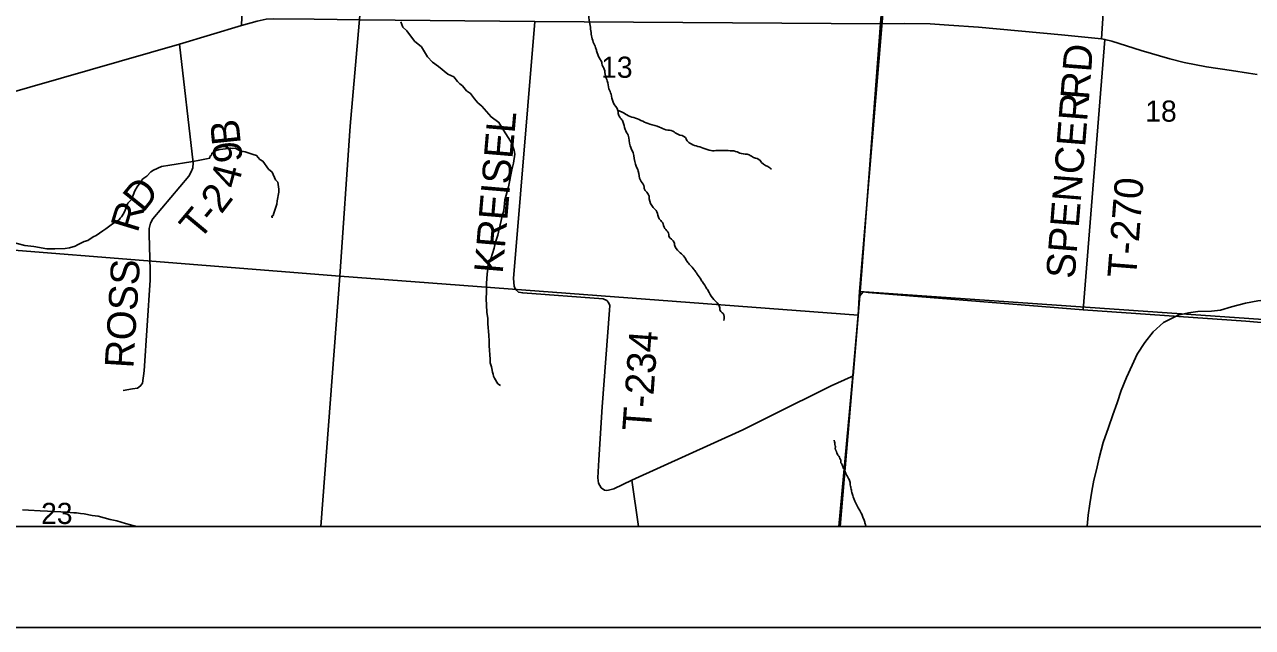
# Model space of a CAD drawing. Extents: x 0 to 42.5, y 0 to 22.
# Drawn here: x 4.279 to 5.494, y 14 to 14.597 of the extents above; entities that cross this region are included whole.
import ezdxf

# ---------------------------------------------------------------- set-up
doc = ezdxf.new("R2010")
doc.units = 0
for name, color, linetype in [('GM_X_County_Road', 7, 'Continuous'), ('GM_X_Interchange_Ramps', 7, 'Continuous'), ('GM_X_Minor_River', 7, 'Continuous'), ('GM_X_Section', 7, 'Continuous'), ('GM_X_Section_Text', 7, 'Continuous'), ('GM_X_State_Route', 7, 'Continuous'), ('GM_X_Township_Road', 7, 'Continuous'), ('GM_X_Township_Road_Text', 7, 'Continuous'), ('GM_X_Unincorporated', 7, 'Continuous'), ('SH_Cut_Line', 7, 'Continuous'), ('SH_Data', 7, 'Continuous')]:
    doc.layers.add(name, color=color, linetype=linetype)

msp = doc.modelspace()

# ---------------------------------------------------------------- linework, layer by layer
at = {"layer": 'GM_X_County_Road'}
msp.add_line((4.8867, 14.1), (4.88, 14.1456), dxfattribs=at)
for points in [[(5.097, 14.2481), (5.0988, 14.2489), (5.1055, 14.328), (5.1087, 14.332), (5.1139, 14.3316), (5.3266, 14.3143), (5.4875, 14.303), (5.579, 14.2953)], [(4.88, 14.1456), (4.9899, 14.1955), (5.018, 14.2096), (5.0772, 14.239), (5.097, 14.2481)]]:
    msp.add_lwpolyline(points, dxfattribs=at)
at = {"layer": 'GM_X_Interchange_Ramps'}
for points in [[(2.1, 14.1), (5.0849, 14.1), (5.0987, 14.2492), (5.1054, 14.3283), (5.1076, 14.3533), (5.1259, 14.5975), (5.1421, 14.8012), (5.162, 15.0772)], [(5.162, 15.0772), (5.1421, 14.8012), (5.1259, 14.5975), (5.1076, 14.3533), (5.1054, 14.3283), (5.0987, 14.2492), (5.0849, 14.1), (8.0699, 14.1)]]:
    msp.add_lwpolyline(points, dxfattribs=at)
at = {"layer": 'GM_X_Minor_River'}
for points in [[(4.6515, 14.5993), (4.6533, 14.5941), (4.6574, 14.5905), (4.6651, 14.5802), (4.6719, 14.5746), (4.678, 14.5645), (4.6829, 14.5593), (4.6887, 14.5551), (4.6979, 14.5474), (4.7039, 14.5448), (4.7075, 14.5402), (4.7097, 14.5379), (4.7124, 14.536), (4.7165, 14.531), (4.7204, 14.5285), (4.7242, 14.523), (4.7275, 14.5192), (4.7317, 14.5157), (4.7408, 14.5052), (4.7485, 14.4998), (4.7547, 14.4893), (4.7582, 14.4837), (4.7611, 14.4795), (4.7636, 14.4718), (4.7642, 14.4682), (4.763, 14.4593), (4.7614, 14.4529), (4.7581, 14.4359), (4.7542, 14.4231), (4.7534, 14.4127), (4.7513, 14.4058), (4.7474, 14.3882), (4.7449, 14.3803), (4.7439, 14.3754), (4.7406, 14.3649), (4.7383, 14.3608), (4.7379, 14.3587), (4.7374, 14.3572), (4.7374, 14.3545), (4.7369, 14.35), (4.7363, 14.3404), (4.7361, 14.3317), (4.7358, 14.3256), (4.7365, 14.312), (4.7374, 14.3056), (4.7375, 14.3006), (4.7384, 14.2893), (4.7387, 14.2832), (4.7389, 14.2787), (4.7399, 14.2655), (4.7399, 14.2617), (4.7412, 14.2579), (4.7414, 14.2562), (4.7423, 14.2527), (4.7429, 14.2507), (4.7432, 14.2486), (4.7442, 14.2467), (4.7473, 14.2411), (4.75, 14.2394)], [(4.2642, 14.3819), (4.2794, 14.3778), (4.2883, 14.377), (4.3012, 14.3748), (4.3092, 14.3746), (4.3195, 14.3751), (4.3237, 14.3756), (4.3294, 14.3773), (4.3317, 14.3786), (4.3382, 14.3818), (4.3418, 14.3829), (4.3471, 14.3865), (4.35, 14.388), (4.3567, 14.3925), (4.3595, 14.3944), (4.3662, 14.3994), (4.3727, 14.4034), (4.374, 14.4049), (4.375, 14.4064), (4.3775, 14.41), (4.3788, 14.413), (4.3815, 14.4197), (4.3851, 14.4236), (4.3882, 14.432), (4.3905, 14.4361), (4.3961, 14.4439), (4.4003, 14.4467), (4.4041, 14.4509), (4.4067, 14.4524), (4.4148, 14.4561), (4.4231, 14.4576), (4.4437, 14.4607), (4.4509, 14.4621), (4.4625, 14.4645), (4.4625, 14.4659), (4.4641, 14.4674), (4.4644, 14.4691), (4.4658, 14.47), (4.466, 14.4713), (4.4723, 14.473), (4.4755, 14.4734), (4.4831, 14.4743), (4.4854, 14.4739), (4.4877, 14.4742), (4.4926, 14.4717), (4.4975, 14.4707), (4.5055, 14.468), (4.5088, 14.4671), (4.512, 14.4632), (4.515, 14.4613), (4.5205, 14.4535), (4.5241, 14.4504), (4.5275, 14.443), (4.5299, 14.4405), (4.5307, 14.4336), (4.5308, 14.4306), (4.5293, 14.4223), (4.5287, 14.419), (4.526, 14.4101), (4.5252, 14.4078), (4.5239, 14.4071), (4.5243, 14.4054)], [(5.3303, 14.1), (5.3303, 14.1003), (5.3315, 14.111), (5.3331, 14.1223), (5.3351, 14.1348), (5.3371, 14.1458), (5.3395, 14.156), (5.3422, 14.1678), (5.3461, 14.1829), (5.3515, 14.198), (5.3558, 14.2105), (5.3601, 14.2223), (5.3639, 14.2344), (5.3694, 14.2472), (5.3748, 14.2597), (5.3798, 14.2703), (5.3874, 14.282), (5.3958, 14.2925), (5.4058, 14.3016), (5.4206, 14.309), (5.4308, 14.3112), (5.4399, 14.3127), (5.4535, 14.3129), (5.4623, 14.314), (5.4733, 14.3173), (5.4869, 14.321)], [(5.4869, 14.321), (5.4994, 14.3232), (5.5112, 14.3246), (5.5206, 14.3241), (5.5346, 14.324), (5.5471, 14.3232), (5.557, 14.3223), (5.5675, 14.3211), (5.5804, 14.3191), (5.5899, 14.3175), (5.6137, 14.3143), (5.6223, 14.3104), (5.6291, 14.3005), (5.6339, 14.2875), (5.6365, 14.2777), (5.6383, 14.2685), (5.6405, 14.2594), (5.6423, 14.2495), (5.6509, 14.2404), (5.6584, 14.2316), (5.661, 14.2205), (5.6654, 14.2087), (5.6695, 14.1977), (5.6732, 14.1893)], [(4.2771, 14.1164), (4.2832, 14.1161), (4.2946, 14.1155), (4.302, 14.115), (4.315, 14.1144), (4.3207, 14.114), (4.3281, 14.1133), (4.3306, 14.1135), (4.3347, 14.1127), (4.3382, 14.1123), (4.3461, 14.1109), (4.352, 14.11), (4.3638, 14.1068), (4.3705, 14.1055), (4.3792, 14.1027), (4.3839, 14.1017), (4.3907, 14.1)]]:
    msp.add_lwpolyline(points, dxfattribs=at)
for points in [[(4.8478, 15.0093), (4.8579, 14.9979), (4.8659, 14.9923), (4.8672, 14.9887), (4.8723, 14.9856), (4.8736, 14.9846), (4.873, 14.9746), (4.8718, 14.9669), (4.8677, 14.9406), (4.8634, 14.9244), (4.862, 14.9152), (4.8598, 14.8967), (4.86, 14.8914), (4.8604, 14.8749), (4.8609, 14.8662), (4.8611, 14.8611), (4.8623, 14.849), (4.8628, 14.8428), (4.8632, 14.8388), (4.865, 14.8278), (4.8659, 14.8242), (4.8674, 14.8193), (4.8687, 14.8151), (4.8686, 14.8075), (4.8676, 14.7981), (4.8555, 14.7663), (4.8535, 14.7541), (4.8451, 14.7279), (4.8418, 14.7166), (4.8412, 14.7107), (4.8409, 14.6962), (4.841, 14.692), (4.8409, 14.6684), (4.8403, 14.6616), (4.84, 14.6569), (4.839, 14.6459), (4.8384, 14.6414), (4.8372, 14.6344), (4.8364, 14.6261), (4.8364, 14.6231), (4.8366, 14.6186), (4.8366, 14.6165), (4.8369, 14.614), (4.8372, 14.6074), (4.8381, 14.5991), (4.8392, 14.5921), (4.8418, 14.5793), (4.8442, 14.5738), (4.8451, 14.5706), (4.8479, 14.5634), (4.8499, 14.5601), (4.851, 14.5558), (4.8527, 14.5525), (4.8538, 14.5459), (4.8557, 14.541), (4.8573, 14.533), (4.8595, 14.5277), (4.8614, 14.5197), (4.8662, 14.5115), (4.8668, 14.5075), (4.8686, 14.5043), (4.8712, 14.5005), (4.8734, 14.4927), (4.8762, 14.4872), (4.8784, 14.4765), (4.8812, 14.4697), (4.8836, 14.4583), (4.8864, 14.4515), (4.8884, 14.4426), (4.8918, 14.4372), (4.8923, 14.4344), (4.897, 14.4269), (4.8973, 14.4241), (4.9012, 14.4157), (4.9046, 14.4113), (4.907, 14.4045), (4.9102, 14.4007), (4.9126, 14.3948), (4.9162, 14.3902), (4.9167, 14.3873), (4.9218, 14.381), (4.9223, 14.3786), (4.9268, 14.3717), (4.9311, 14.3677), (4.9347, 14.3621), (4.9375, 14.3587), (4.9418, 14.3539), (4.9438, 14.3508), (4.9476, 14.3455), (4.9498, 14.3419), (4.9543, 14.3352), (4.9565, 14.3314), (4.961, 14.3245), (4.9668, 14.3171), (4.9673, 14.3135), (4.9702, 14.3106), (4.9711, 14.3039)], [(4.8662, 14.5115), (4.8711, 14.5097), (4.8766, 14.5064), (4.8837, 14.5039), (4.8978, 14.498), (4.9073, 14.4952), (4.9137, 14.4925), (4.9206, 14.4911), (4.9255, 14.488), (4.933, 14.4847), (4.9342, 14.4824), (4.9373, 14.4793), (4.9505, 14.4744), (4.9584, 14.4718), (4.9645, 14.4719), (4.9754, 14.4718), (4.9826, 14.4711), (4.9884, 14.4689), (4.996, 14.4677), (5.0005, 14.4652), (5.0071, 14.4621), (5.0084, 14.4601), (5.0165, 14.4549), (5.0181, 14.4536)]]:
    msp.add_spline(points, degree=3, dxfattribs=at)
msp.add_open_spline([(5.1114, 14.1), (5.1113, 14.1007), (5.1113, 14.1014), (5.111, 14.1021), (5.1097, 14.1062), (5.1083, 14.1103), (5.1064, 14.1141), (5.1055, 14.1158), (5.1045, 14.1174), (5.1036, 14.119), (5.1022, 14.1217), (5.1008, 14.1244), (5.0997, 14.1272), (5.098, 14.1315), (5.0972, 14.1359), (5.0962, 14.1403), (5.0959, 14.1419), (5.0961, 14.1436), (5.0955, 14.1451), (5.0944, 14.1475), (5.0931, 14.1499), (5.0919, 14.1523), (5.0903, 14.1557), (5.0887, 14.1591), (5.0871, 14.1626), (5.0866, 14.1636), (5.0868, 14.1649), (5.0864, 14.166), (5.0854, 14.1684), (5.0838, 14.1705), (5.0828, 14.1728), (5.0826, 14.1735), (5.0823, 14.1741), (5.0821, 14.1748), (5.0818, 14.1754), (5.0814, 14.176), (5.0812, 14.1767), (5.0809, 14.1773), (5.0815, 14.178), (5.0814, 14.1787), (5.081, 14.1809), (5.0806, 14.183), (5.0803, 14.1852)], degree=3, dxfattribs=at)
at = {"layer": 'GM_X_Section'}
for points in [[(4.1061, 14.8789), (4.6315, 14.8399), (4.6015, 14.4962), (4.591, 14.3476), (4.0702, 14.3893)], [(5.6186, 14.8156), (5.5806, 14.2995), (5.1051, 14.3325), (5.1432, 14.7839), (5.1456, 14.8014), (5.149, 14.8472)], [(5.1456, 14.8014), (5.1432, 14.7839), (5.1051, 14.3325), (5.1039, 14.3089), (4.591, 14.3476), (4.6015, 14.4962), (4.6315, 14.8399)]]:
    msp.add_lwpolyline(points, close=True, dxfattribs=at)
at = {"layer": 'GM_X_State_Route'}
msp.add_line((4.4324, 14.5772), (4.4938, 14.5956), dxfattribs=at)
for points in [[(4.4938, 14.5956), (4.5095, 14.6001), (4.5183, 14.6019), (4.5254, 14.6023), (4.5656, 14.6019), (4.6111, 14.6014), (4.7841, 14.5997), (5.126, 14.5972), (5.1502, 14.5976), (5.1752, 14.5973), (5.1936, 14.5961), (5.223, 14.5939), (5.3051, 14.5864), (5.3447, 14.5826)], [(3.9467, 14.4189), (3.9682, 14.4252), (4.0682, 14.4649), (4.091, 14.4739), (4.2559, 14.5263), (4.4324, 14.5772)], [(5.3447, 14.5826), (5.348, 14.5819), (5.3547, 14.5803), (5.3839, 14.571), (5.4123, 14.5627), (5.4264, 14.559), (5.4485, 14.5547), (5.4731, 14.551), (5.4901, 14.5484), (5.4985, 14.5473)]]:
    msp.add_lwpolyline(points, dxfattribs=at)
at = {"layer": 'GM_X_Township_Road'}
for p, q in [((4.4324, 14.5772), (4.4938, 14.5956)), ((5.3266, 14.3143), (5.348, 14.5819)), ((4.8867, 14.1), (4.88, 14.1456))]:
    msp.add_line(p, q, dxfattribs=at)
for points in [[(4.4938, 14.5956), (4.4984, 14.7091), (4.5015, 14.7564), (4.5015, 14.7659), (4.5012, 14.7787), (4.5027, 14.7842), (4.5113, 14.8055), (4.5194, 14.8266), (4.5208, 14.8325), (4.5216, 14.8437), (4.5273, 14.974), (4.5267, 14.9763), (4.5249, 14.9784), (4.3899, 15.0041), (4.381, 15.0054), (4.3784, 15.0076), (4.3767, 15.0097), (4.3647, 15.0772)], [(5.3447, 14.5826), (5.3462, 14.608), (5.3809, 15.0772)], [(4.88, 14.1456), (4.8622, 14.1373), (4.8595, 14.1364), (4.8569, 14.1357), (4.8548, 14.1355), (4.8529, 14.1357), (4.8495, 14.1382), (4.8471, 14.1428), (4.8464, 14.148), (4.8474, 14.1658), (4.8508, 14.2183), (4.858, 14.3141), (4.8581, 14.3185), (4.8568, 14.3217), (4.8551, 14.3236), (4.8517, 14.3252), (4.7721, 14.331), (4.7678, 14.3319), (4.765, 14.3344), (4.7637, 14.3378), (4.763, 14.3452), (4.7841, 14.5997)], [(4.3769, 14.2346), (4.386, 14.2361), (4.391, 14.2369), (4.3941, 14.239), (4.396, 14.2418), (4.3976, 14.2539), (4.4035, 14.3437), (4.4035, 14.3534), (4.4026, 14.389), (4.4025, 14.3949), (4.4038, 14.4), (4.4062, 14.4045), (4.4417, 14.4466), (4.4442, 14.4507), (4.4456, 14.4547), (4.4459, 14.4596), (4.4324, 14.5772)]]:
    msp.add_lwpolyline(points, dxfattribs=at)
at = {"layer": 'GM_X_Unincorporated'}
for points in [[(4.0491, 14.1), (4.5722, 14.1), (4.591, 14.3476), (4.0702, 14.3893)], [(4.5722, 14.1), (5.0862, 14.1), (5.1039, 14.3089), (4.591, 14.3476)], [(5.0862, 14.1), (5.5684, 14.1), (5.5806, 14.2995), (5.1051, 14.3325), (5.1039, 14.3089)]]:
    msp.add_lwpolyline(points, close=True, dxfattribs=at)
at = {"layer": 'SH_Cut_Line'}
msp.add_lwpolyline([(2.1, 14.1), (8.0699, 14.1)], dxfattribs=at)
at = {"layer": 'SH_Data'}
for p, q in [((2.1, 14.1), (8.9, 14.1)), ((2, 14), (9, 14))]:
    msp.add_line(p, q, dxfattribs=at)

# ---------------------------------------------------------------- texts
at = {"layer": 'GM_X_Section_Text'}
for s, p in [('13', (4.8496, 14.5439)), ('18', (5.3879, 14.5005)), ('23', (4.2956, 14.1024))]:
    msp.add_text(s, height=0.02093, rotation=0, dxfattribs=at).set_placement(p)
at = {"layer": 'GM_X_Township_Road_Text'}
for s, height, rotation, p in [('RD', 0.02841, 85.5621, (5.3322, 14.5216)), ('SPENCER', 0.02841, 85.4574, (5.318, 14.3445)), ('KREISEL', 0.02841, 85.1391, (4.7522, 14.3496)), ('B', 0.0284, 95.9195, (4.4933, 14.4788)), ('9', 0.0284, 96.4491, (4.4952, 14.4615)), ('4', 0.0284, 75.0209, (4.4898, 14.4331)), ('D', 0.0284, 51.0307, (4.3964, 14.4096)), ('T-270', 0.02841, 85.5158, (5.3787, 14.3452)), ('2', 0.0284, 52.5841, (4.4739, 14.4083)), ('R', 0.0284, 73.1056, (4.391, 14.3898)), ('T', 0.0284, 50.1527, (4.452, 14.382)), ('-', 0.0284, 50.3985, (4.4657, 14.3984)), ('ROSS', 0.02841, 86.4235, (4.3868, 14.256)), ('T-234', 0.02841, 85.8327, (4.8988, 14.1936))]:
    msp.add_text(s, height=height, rotation=rotation, dxfattribs=at).set_placement(p)

doc.saveas('drawing.dxf')
